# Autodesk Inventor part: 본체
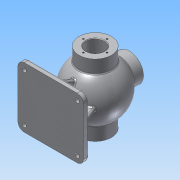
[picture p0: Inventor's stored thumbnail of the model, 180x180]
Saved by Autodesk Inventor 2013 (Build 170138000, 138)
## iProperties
Created: 2018-06
Part Number: 본체
Material: 알루미늄 6061
Document SubType Name: Modeling
Designer: Administrator
Density: 2.71 g/cm^3
Mass: 1509.58 g
Surface Area: 1153.7 cm^2
Volume: 557.041 cm^3
Author: Administrator
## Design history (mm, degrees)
sketch "스케치1"
  geometry: L1 (0, 68)-(0, -68); L2 (0, 68)-(31, 68); L3 (31, -68)-(0, -68); L4 (31, 68)-(31, 42.988); L5 (31, -42.988)-(31, -68); L6 (17.5, 68)-(17.5, 39.278); L7 (17.5, -39.278)-(17.5, -68); A1 r 53 centre (0, 0) between (31, -42.988) and (31, 42.988); A2 r 43 centre (0, 0) between (17.5, -39.278) and (17.5, 39.278); 2 further points
  constraints: 14 end point, 4 point on circle, 2 centre point, 2 coincident, 2 point on line, 1 concentric, 1 midpoint, 1 vertical alignment
  dimensions: "d0" = 136 distance of L1.start L1.end; "d1" = 106 diameter of A1; "d2" = 86 diameter of A2; "d3" = 62 diameter of L4 L1; "d4" = 62 diameter of L5 L1; "d5" = 136 distance between parallel lines of L3 L2; "d6" = 35 diameter of L6 L1; "d7" = 35 diameter of L7 L1
revolve "회전1" sketch "스케치1" stored, may be unused: angle "d8" = 90 deg
node "작업 평면1"
sketch "스케치2"
  geometry: L1 (-62.5, -57.5)-(62.5, -57.5); L2 (62.5, -57.5)-(62.5, 57.5); L3 (62.5, 57.5)-(-62.5, 57.5); L4 (-62.5, 57.5)-(-62.5, -57.5); L5 (-62.5, -57.5)-(62.5, 57.5); L6 (62.5, -57.5)-(-62.5, 57.5); 3 further points
  constraints: 12 end point, 3 midpoint, 2 parallel, 1 coincident, 1 horizontal, 1 perpendicular
  dimensions: "d10" = 125 distance of L3.end L2.end; "d11" = 115 distance of L2.end L1.end
extrude "돌출1" join sketch "스케치2" distance "d12" = 10; taper "d13" = 0 deg
fillet "모깎기1" dims "d14" = 12
node "작업 평면2"
sketch "스케치3"
  geometry: C1 r 27 at (0, 0); 1 further point
  constraints: 1 centre point, 1 coincident
  dimensions: "d16" = 54 diameter of C1
extrude "돌출2" join sketch "스케치3" stored distance "d17" = 10; taper "d18" = 0 deg
hole "구멍1" diameter "d21" = 26; stored, may be unused: countersink angle "d25" = 90 deg, drill point angle "d27" = 0 deg; dims "d19" = 10, "d20" = 10, "d22" = 6, "d23" = 4, "d24" = 2, "d26" = 45
sketch "스케치5"
  geometry: C1 r 31 at (0, 0) reference; 1 further point
  constraints: 1 vertical alignment
  dimensions: "d32" = 22.5 distance of C1.centre point (0, 22.5)
hole "구멍2" sketch "스케치5" at (0, 22.5) diameter "d33" = 3.242; stored, may be unused: countersink angle "d37" = 90 deg, drill point angle "d39" = 118 deg; dims "d34" = 12, "d35" = 4, "d36" = 2, "d38" = 15
sketch "스케치6"
  geometry: L1 (-52.5, -4)-(52.5, -4); L2 (52.5, -4)-(52.5, 4); L3 (52.5, 4)-(-52.5, 4); L4 (-52.5, 4)-(-52.5, -4); L5 (-52.5, -4)-(52.5, 4); L6 (52.5, -4)-(-52.5, 4); 3 further points
  constraints: 12 end point, 3 midpoint, 2 parallel, 1 coincident, 1 horizontal, 1 perpendicular
  dimensions: "d43" = 105 distance of L3.end L2.end; "d44" = 8 distance of L2.end L1.end
extrude "돌출3" join sketch "스케치6" stored distance "d45" = 10; taper "d46" = 0 deg
feature "면 기울기1" dims angle "d47" = 22 deg
sketch "스케치7"
  geometry: L1 (-48.75, 36.894)-(-75, 47.5); L2 (-75, -45.5)-(-75, 45.5) reference; L3 (-85, 57.5)-(-75, 57.5) reference; 1 further point
  constraints: 2 end point, 1 point on line
  dimensions: "d48" = 22 deg angle of L3 L1; "d49" = 10 distance from line of L3 L1.end
feature "리브1" sketch "스케치7" dims "d50" = 1, "d51" = 8, "d52" = 0, "d53" = 0, "d54" = 1, "d55" = 1
sketch "스케치8"
  geometry: C1 r 17.5 at (0, 0) reference; 1 further point
  constraints: 1 vertical alignment
  dimensions: "d56" = 24 distance of C1.centre point (0, 24)
hole "구멍3" sketch "스케치8" at (0, 24) diameter "d57" = 3.242; stored, may be unused: countersink angle "d61" = 90 deg, drill point angle "d63" = 118 deg; dims "d58" = 16, "d59" = 4, "d60" = 2, "d62" = 19
sketch "스케치9"
  geometry: C1 r 13 at (0, 0) reference; 1 further point
  constraints: 1 vertical alignment
  dimensions: "d67" = 20 distance of C1.centre point (0, 20)
hole "구멍4" sketch "스케치9" at (0, 20) diameter "d68" = 3.242; stored, may be unused: countersink angle "d72" = 90 deg, drill point angle "d74" = 118 deg; dims "d69" = 9, "d70" = 4, "d71" = 2, "d73" = 11
node "작업 평면4"
sketch "스케치10"
  geometry: L1 (-65, -27)-(-65, 27) reference; 3 further points
  constraints: 1 horizontal alignment, 1 midpoint, 1 other
  dimensions: "d80" = 10 distance from line of point (-55, 0) L1
feature "엠보싱1" sketch "스케치10" dims "d0" = 136, "d12" = 10, "d81" = 0.5, "d82" = 0
node "작업 평면5"
sketch "스케치11"
  geometry: C1 r 18.5 at (0, 0); 1 further point
  constraints: 1 centre point, 1 coincident
  dimensions: "d84" = 37 diameter of C1
extrude "돌출4" cut sketch "스케치11" distance "d85" = 1.75; taper "d86" = 0 deg
fillet "모깎기2" dims "d87" = 3
fillet "모깎기3" dims "d88" = 3
fillet "모깎기4" dims "d89" = 3
fillet "모깎기5" dims "d90" = 3
chamfer "모따기1" distance "d91" = 1; stored, may be unused: second distance "d92" = 2, angle "d93" = 45 deg
chamfer "모따기2" distance "d94" = 1; stored, may be unused: second distance "d95" = 2, angle "d96" = 45 deg
hole "구멍5" diameter "d99" = 8; stored, may be unused: countersink angle "d103" = 90 deg, drill point angle "d105" = 0 deg; dims "d97" = 10, "d98" = 10, "d100" = 9, "d101" = 12, "d102" = 3, "d104" = 10
fillet "모깎기6" dims "d106" = 3
fillet "모깎기7" dims "d107" = 3
node "솔리드1"
pattern_circular "원형 패턴1" dims angle "d41" = 360 deg
mirror "대칭1"
pattern_circular "원형 패턴2" dims angle "d65" = 360 deg
pattern_circular "원형 패턴3" dims angle "d76" = 360 deg
mirror "대칭2"
mirror "대칭3"
other parameters: "d9" = -85, "d79" = -27, "d83" = -16
